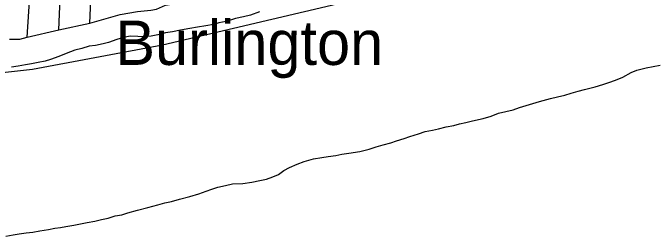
# Model space of a CAD drawing. Extents: x 1949938.81 to 1949945.61, y 152207.65 to 152214.09.
# Drawn here: x 1949943.289 to 1949944.431, y 152207.761 to 152208.158 of the extents above; entities that cross this region are included whole.
import ezdxf

# ---------------------------------------------------------------- set-up
doc = ezdxf.new("R2010")
doc.units = 0
for name, color, linetype in [('GM_X_County', 7, 'Continuous'), ('GM_X_County_Road', 7, 'Continuous'), ('GM_X_Major_River', 7, 'Continuous'), ('GM_X_Township', 7, 'Continuous'), ('GM_X_Township_Subdivision', 7, 'Continuous'), ('GM_X_Unincorporated_Text', 7, 'Continuous')]:
    doc.layers.add(name, color=color, linetype=linetype)

msp = doc.modelspace()

# ---------------------------------------------------------------- linework, layer by layer
at = {"layer": 'GM_X_County'}
msp.add_lwpolyline([(1949942.5103, 152208.0107), (1949942.8268, 152208.0046), (1949942.9926, 152208.0073), (1949943.0418, 152208.019), (1949943.1902, 152208.0433), (1949943.3242, 152208.0581), (1949943.5551, 152208.1009), (1949944.0013, 152208.2067), (1949944.0649, 152208.2317), (1949944.5237, 152208.3846), (1949944.9116, 152208.528), (1949945.0312, 152208.5697), (1949945.2633, 152208.6645), (1949945.3744, 152208.725), (1949945.418, 152208.7524), (1949945.4377, 152208.7581), (1949945.4771, 152208.7673), (1949945.504, 152208.7825), (1949945.5586, 152208.8115), (1949945.5958, 152208.8237), (1949945.6069, 152208.8266)], dxfattribs=at)
at = {"layer": 'GM_X_County_Road'}
msp.add_lwpolyline([(1949943.2833, 152208.1115), (1949943.3015, 152208.1115), (1949943.3146, 152208.1145), (1949943.3709, 152208.128), (1949943.4256, 152208.1398), (1949943.4795, 152208.155), (1949943.5105, 152208.1607), (1949943.5341, 152208.1628), (1949943.5442, 152208.1648), (1949943.5604, 152208.1715), (1949943.5851, 152208.1756), (1949943.6548, 152208.1883), (1949943.6743, 152208.1933), (1949943.684, 152208.1959), (1949943.6884, 152208.1978), (1949943.6911, 152208.2011)], dxfattribs=at)
at = {"layer": 'GM_X_Major_River'}
for points in [[(1949943.7271, 152208.1596), (1949943.7112, 152208.1539), (1949943.6984, 152208.1509), (1949943.6844, 152208.1479), (1949943.6678, 152208.1429), (1949943.6549, 152208.1403), (1949943.6451, 152208.1376), (1949943.6318, 152208.135), (1949943.6171, 152208.1323), (1949943.6031, 152208.1301), (1949943.5868, 152208.1274), (1949943.5728, 152208.1244), (1949943.56, 152208.1225), (1949943.5464, 152208.1191), (1949943.5346, 152208.1164), (1949943.5218, 152208.1153), (1949943.5112, 152208.1161), (1949943.498, 152208.1168), (1949943.4877, 152208.1149), (1949943.4738, 152208.1108), (1949943.459, 152208.1055), (1949943.4492, 152208.1032), (1949943.4356, 152208.1002), (1949943.4246, 152208.0986), (1949943.4114, 152208.0949), (1949943.3989, 152208.0914), (1949943.3837, 152208.0858), (1949943.3705, 152208.0801), (1949943.3561, 152208.0748)], [(1949943.3561, 152208.0748), (1949943.3463, 152208.0721), (1949943.3342, 152208.0695), (1949943.3221, 152208.0672), (1949943.3115, 152208.0653), (1949943.2987, 152208.0634), (1949943.2866, 152208.0615)], [(1949944.1646, 152207.9827), (1949944.1774, 152207.9858), (1949944.1888, 152207.9895), (1949944.2066, 152207.9952), (1949944.2243, 152208.0005), (1949944.2436, 152208.0055), (1949944.2565, 152208.0089), (1949944.2693, 152208.0115), (1949944.2803, 152208.0153), (1949944.2928, 152208.0187), (1949944.3045, 152208.0214), (1949944.3234, 152208.0267), (1949944.3367, 152208.0304), (1949944.3476, 152208.0342), (1949944.3594, 152208.0384), (1949944.3722, 152208.0437), (1949944.3873, 152208.0517), (1949944.3972, 152208.0558), (1949944.4138, 152208.06), (1949944.4263, 152208.0623), (1949944.4384, 152208.0649)], [(1949943.2763, 152207.7608), (1949943.2895, 152207.7631), (1949943.3005, 152207.7649), (1949943.3129, 152207.7665), (1949943.3243, 152207.768), (1949943.3371, 152207.7702), (1949943.3526, 152207.7725), (1949943.3636, 152207.7748), (1949943.3734, 152207.7759), (1949943.3833, 152207.7782), (1949943.3976, 152207.7805), (1949943.409, 152207.7827), (1949943.4211, 152207.785), (1949943.4347, 152207.7877), (1949943.4464, 152207.7907), (1949943.4582, 152207.7926), (1949943.4706, 152207.7967), (1949943.4827, 152207.799), (1949943.4933, 152207.8024), (1949943.5107, 152207.807), (1949943.5289, 152207.8119), (1949943.5466, 152207.8168), (1949943.5591, 152207.8199), (1949943.5709, 152207.8225), (1949943.5852, 152207.8263), (1949943.6034, 152207.8312), (1949943.6196, 152207.8361), (1949943.6321, 152207.8411), (1949943.6423, 152207.8445), (1949943.6529, 152207.8479), (1949943.6665, 152207.8509), (1949943.679, 152207.8536), (1949943.6972, 152207.8547), (1949943.7134, 152207.857), (1949943.7274, 152207.86), (1949943.7395, 152207.8623), (1949943.7509, 152207.8664), (1949943.7607, 152207.8706), (1949943.7705, 152207.8778), (1949943.7804, 152207.8827), (1949943.794, 152207.8888), (1949943.8061, 152207.8937), (1949943.8231, 152207.8983), (1949943.8375, 152207.9005), (1949943.8492, 152207.9024), (1949943.8624, 152207.9043), (1949943.873, 152207.9066), (1949943.8859, 152207.9085), (1949943.9055, 152207.9115), (1949943.9218, 152207.9153), (1949943.9343, 152207.9195), (1949943.9464, 152207.9233), (1949943.96, 152207.9267), (1949943.9702, 152207.9305), (1949943.9838, 152207.9346), (1949943.994, 152207.938), (1949944.0095, 152207.943), (1949944.0213, 152207.9467), (1949944.0341, 152207.9494), (1949944.0451, 152207.952), (1949944.0587, 152207.9551), (1949944.0719, 152207.9577), (1949944.0825, 152207.9608), (1949944.0935, 152207.963), (1949944.1052, 152207.9657), (1949944.1241, 152207.9698), (1949944.1385, 152207.9744), (1949944.1517, 152207.9793), (1949944.1646, 152207.9827)]]:
    msp.add_lwpolyline(points, dxfattribs=at)
at = {"layer": 'GM_X_Township'}
msp.add_lwpolyline([(1949942.5103, 152208.0107), (1949942.8268, 152208.0046), (1949942.9926, 152208.0073), (1949943.0418, 152208.019), (1949943.1902, 152208.0433), (1949943.3242, 152208.0581), (1949943.5551, 152208.1009), (1949944.0013, 152208.2067), (1949944.0649, 152208.2317), (1949944.5237, 152208.3846), (1949944.9116, 152208.528), (1949945.0312, 152208.5697), (1949945.2633, 152208.6645), (1949945.3744, 152208.725), (1949945.418, 152208.7524), (1949945.4377, 152208.7581), (1949945.4771, 152208.7673), (1949945.504, 152208.7825), (1949945.5586, 152208.8115), (1949945.5958, 152208.8237), (1949945.6069, 152208.8266)], dxfattribs=at)
at = {"layer": 'GM_X_Township_Subdivision'}
for points in [[(1949943.4256, 152208.1398), (1949943.4296, 152208.2228), (1949943.4313, 152208.2339), (1949943.4347, 152208.2781), (1949943.4362, 152208.3128), (1949943.4391, 152208.3771), (1949943.4413, 152208.4052), (1949943.442, 152208.485), (1949943.4425, 152208.5435)], [(1949943.3709, 152208.128), (1949943.375, 152208.2262), (1949943.3813, 152208.3159), (1949943.3856, 152208.3762), (1949943.3841, 152208.409), (1949943.3806, 152208.4818), (1949943.3807, 152208.4824)], [(1949943.3146, 152208.1145), (1949943.319, 152208.1884), (1949943.3209, 152208.2238)]]:
    msp.add_lwpolyline(points, dxfattribs=at)

# ---------------------------------------------------------------- texts
at = {"layer": 'GM_X_Unincorporated_Text'}
msp.add_text('Burlington', height=0.07898, rotation=0, dxfattribs=at).set_placement((1949943.4711, 152208.0654))

doc.saveas('drawing.dxf')
